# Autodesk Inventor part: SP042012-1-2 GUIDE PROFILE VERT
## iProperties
Created: 2012-04
Part Number: SP042012-1-2 GUIDE PROFILE VERT
Material: PVC-U
Document SubType Name: Modeling
Designer: Administrator
Density: 1.4 g/cm^3
Mass: 218.823 g
Surface Area: 1516.36 cm^2
Volume: 156.302 cm^3
Author: Administrator
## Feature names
1. Extrusion1
